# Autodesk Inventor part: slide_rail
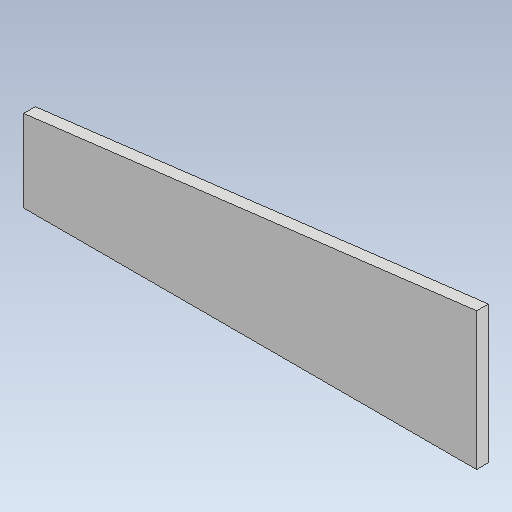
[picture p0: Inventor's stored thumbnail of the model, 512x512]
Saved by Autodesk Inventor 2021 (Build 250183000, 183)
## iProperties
Created: 2026-10
Part Number: slide_rail
Material: Generic
Document SubType Name: Modeling
Designer: alolo
Density: 1 g/cm^3
Appearance: Default
Author: alolo
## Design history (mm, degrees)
sketch "Sketch1"
  geometry: L1 (0, 35)-(193.546, 58.765); L2 (0, 35)-(193.546, 35); L3 (193.546, 35)-(193.546, 58.765); L4 (0, 35)-(0, 0); L5 (0, 0)-(193.546, 0); L6 (193.546, 0)-(193.546, 35); 1 further point
  constraints: 12 end point, 2 perpendicular, 2 vertical, 1 coincident, 1 horizontal
  dimensions: "d3" = 195 distance of L1.start L1.end (= slide_length); "d4" = 7 deg angle of L1 L2 (= slide_angle); "d5" = 35 distance of L1.start L4.end
extrude "Extrusion1" new body sketch "Sketch1" distance "d6" = 5 (= wood_thickness); taper "d7" = 0 deg
body "Solid1"
other parameters: "slide_length" = 195 [user parameter; used in 1 equation term], "slide_angle" = 7 deg [user parameter; used in 1 equation term], "slide_width" = 65 [user parameter], "wood_thickness" = 5 [user parameter; used in 1 equation term], "aclyric_thickness" = 6 [user parameter]
